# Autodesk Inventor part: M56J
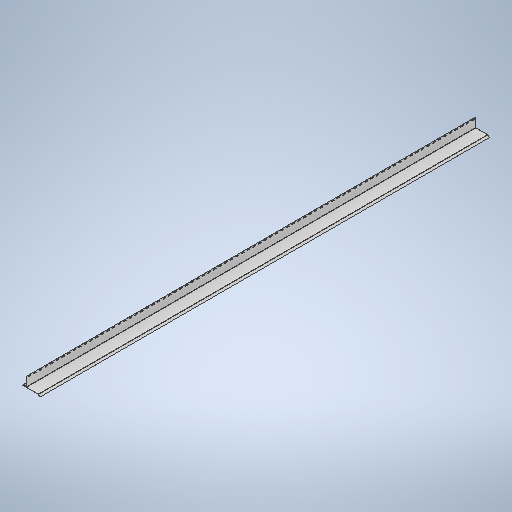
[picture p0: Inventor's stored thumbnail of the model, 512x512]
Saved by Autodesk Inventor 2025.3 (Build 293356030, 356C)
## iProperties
Created: 2024-06
Part Number: M56J
Material: Generic
Document SubType Name: Modeling
Designer: mathieu.gyimah-chias
Density: 1 g/cm^3
Appearance: Default
Author: mathieu.gyimah-chias
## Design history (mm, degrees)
sketch "Sketch1"
  geometry: L1 (-51.624, -22.987)-(28.703, -23.001); L2 (-52.248, 40.005)-(-52.259, -22.352); L3 (-52.756, 40.005)-(-52.248, 40.005); L4 (-52.767, -22.352)-(-52.756, 40.005); L5 (28.703, -23.509)-(-51.624, -23.495); L6 (40.419, -34.651)-(29.691, -23.919); L7 (29.68, -24.41)-(40.168, -34.902); L8 (-77.488, -23.834)-(28.333, -23.852); L9 (-65.467, -23.493)-(-77.488, -23.491); L10 (-65.467, -22.985)-(-65.467, -23.493); L11 (-77.488, -22.983)-(-65.467, -22.985); L12 (28.333, -24.36)-(-77.488, -24.342); L13 (39.808, -35.261)-(29.321, -24.77); L14 (30.05, -23.56)-(40.778, -34.291); A1 r 1.905 centre (28.703, -24.906) between (30.05, -23.56) and (28.703, -23.001); A2 r 0.635 centre (-51.624, -22.352) between (-52.259, -22.352) and (-51.624, -22.987); A3 r 1.143 centre (-51.624, -22.352) between (-52.767, -22.352) and (-51.624, -23.495); A4 r 1.397 centre (28.703, -24.906) between (29.691, -23.919) and (28.703, -23.509); A5 r 0.178 centre (40.293, -34.776) between (40.168, -34.902) and (40.419, -34.651); A6 r 1.905 centre (28.333, -25.757) between (29.68, -24.41) and (28.333, -23.852); A7 r 0.171 centre (-77.488, -23.662) between (-77.488, -23.491) and (-77.488, -23.834); A8 r 0.679 centre (-77.488, -23.662) between (-77.488, -22.983) and (-77.488, -24.342); A9 r 1.397 centre (28.333, -25.757) between (29.321, -24.77) and (28.333, -24.36); A10 r 0.686 centre (40.293, -34.776) between (39.808, -35.261) and (40.778, -34.291); 4 further points
  constraints: 28 end point, 22 point on circle, 20 tangent, 10 centre point, 9 parallel, 3 perpendicular
  dimensions: "d0" = 0.508 distance between parallel lines of L2 L4; "d1" = 0.508 distance between parallel lines of L5 L1; "d2" = 0.508 distance between parallel lines of L14 L6; "d3" = 0.508 distance between parallel lines of L13 L7; "d4" = 0.508 distance between parallel lines of L12 L8; "d5" = 0.508 distance between parallel lines of L11 L9; "d6" = 0.3429 distance between parallel lines of L8 L5; "d7" = 135 deg angle of L14 L1; "d9" = 0.3429 distance between parallel lines of L8 L9; "d10" = 0 distance of A3.centre A2.centre; "d11" = 0 distance of A4.centre A1.centre; "d12" = 0 distance of A6.centre A9.centre; "d13" = 0 distance of A7.centre A8.centre; "d14" = 1.143 radius of A3; "d15" = 1.905 radius of A1; "d16" = 1.905 radius of A6; "d17" = 15.875 distance of point (40.778, -35.261) L14.start; "d18" = 25.4 distance from line of L4 point (-78.167, -23.662); "d19" = 12.7 distance from line of L10 point (-78.167, -23.662); "d20" = 63.5 distance between parallel lines of L3 L5; "d21" = 80.9625 distance from line of L2 L1.end; "d25" = 0.6858 radius of A10
extrude "Extrusion1" new body sketch "Sketch1" distance "d23" = 3048; taper "d24" = 0 deg
sketch "Sketch2"
  geometry: L1 (3022.994, 52.045)-(3038.081, 52.045); L2 (3038.081, 56.007)-(3022.994, 56.007); L3 (0, 62.357)-(3048, 62.357) reference; L4 (3048, 62.357)-(3048, 0) reference; A1 r 1.981 centre (3038.081, 54.026) between (3038.081, 52.045) and (3038.081, 56.007); A2 r 1.981 centre (3022.994, 54.026) between (3022.994, 56.007) and (3022.994, 52.045); 3 further points
  constraints: 6 point on circle, 4 end point, 4 tangent, 2 centre point, 2 horizontal
  dimensions: "d26" = 3.9624 distance between parallel lines of L1 L2; "d27" = 6.35 distance between parallel lines of L3 L2; "d28" = 7.9375 distance from line of L4 point (3040.062, 54.026); "d29" = 19.05 distance of point (3040.062, 54.026) point (3021.013, 54.026)
extrude "Extrusion2" cut sketch "Sketch2" distance "d30" = 25.4; taper "d31" = 0 deg
body "Solid1"
pattern_linear "Rectangular Pattern1" dims "d34" = 38.1
